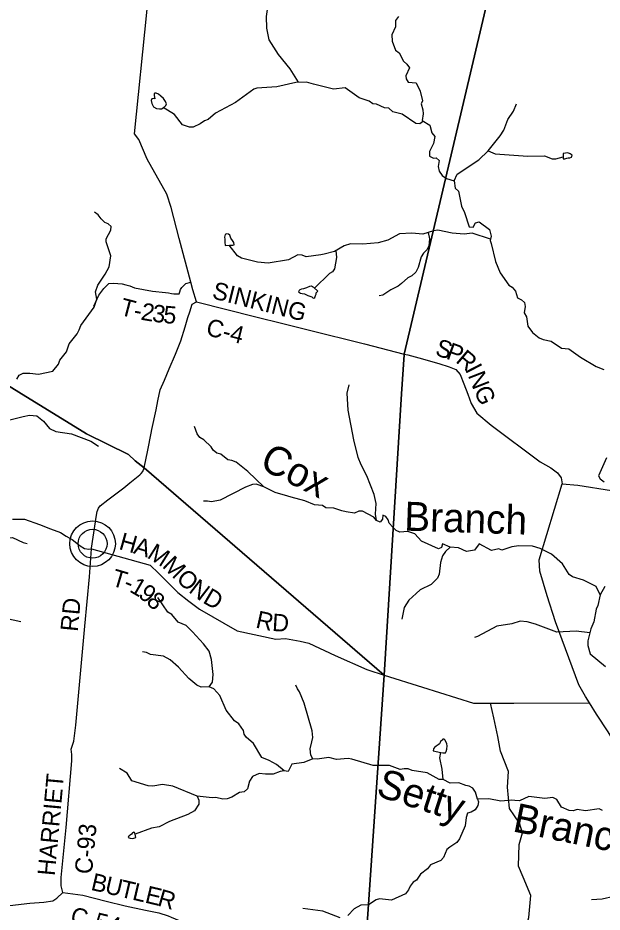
# Model space of a CAD drawing. Extents: x 1525783 to 1900577, y 218250 to 627376.
# Drawn here: x 1686297 to 1696377, y 391777 to 407202 of the extents above; entities that cross this region are included whole.
import ezdxf

# ---------------------------------------------------------------- set-up
doc = ezdxf.new("R2010")
doc.units = 0
for name, color, linetype in [('GM_X_County_Road', 7, 'Continuous'), ('GM_X_County_Road_Text', 7, 'Continuous'), ('GM_X_Minor_Lake', 7, 'Continuous'), ('GM_X_Minor_River', 7, 'Continuous'), ('GM_X_Minor_River_Text', 7, 'Continuous'), ('GM_X_Township', 7, 'Continuous'), ('GM_X_Township_Road', 7, 'Continuous'), ('GM_X_Township_Road_Text', 7, 'Continuous'), ('GM_X_Township_ROW', 7, 'Continuous'), ('GM_X_Unincorporated', 7, 'Continuous'), ('GM_X_Unincorporated_Location', 7, 'Continuous')]:
    doc.layers.add(name, color=color, linetype=linetype)

msp = doc.modelspace()

# ---------------------------------------------------------------- linework, layer by layer
at = {"layer": 'GM_X_County_Road'}
for points in [[(1689376, 402305), (1689315, 402509), (1689280, 402641), (1689079, 403395), (1688943, 403934), (1688868, 404164), (1688526, 404763), (1688383, 405107), (1688311, 405205), (1688519, 407298), (1688611, 408295), (1688572, 408507), (1688365, 408841), (1688235, 409123), (1688204, 409341), (1688156, 409567), (1688118, 409667), (1687991, 409731), (1687933, 409730), (1688006, 410518), (1688100, 411267), (1688235, 412775)], [(1688231, 399183), (1688399, 399321), (1688426, 399344), (1688450, 399380), (1688475, 399440), (1688539, 399748), (1688594, 400037), (1688606, 400101), (1688681, 400443), (1688714, 400597), (1688751, 400786), (1688826, 400955), (1688907, 401149), (1689018, 401403), (1689108, 401634), (1689183, 401871), (1689230, 402035), (1689263, 402130), (1689303, 402265), (1689376, 402305)], [(1689376, 402305), (1690403, 402046), (1690870, 401929), (1691308, 401821), (1692276, 401581), (1692963, 401404), (1693024, 401388)], [(1693024, 401388), (1693213, 401340), (1693562, 401238), (1693736, 401183), (1693851, 401135), (1693925, 401052), (1693991, 400892), (1694058, 400714), (1694117, 400550), (1694218, 400382), (1694460, 400177), (1695307, 399545), (1695493, 399438), (1695608, 399356), (1695669, 399269), (1695689, 399162), (1695956, 399142), (1696541, 399047)], [(1687568, 398044), (1687569, 398056), (1687654, 398627), (1687663, 398687), (1687686, 398743), (1687718, 398784), (1687848, 398890), (1688123, 399094), (1688231, 399183)], [(1698028, 391638), (1697920, 392012), (1697790, 392354), (1697577, 392945), (1697433, 393255), (1697123, 393824), (1697042, 393959), (1696781, 394389), (1696480, 394888), (1696280, 395190), (1696157, 395389), (1696091, 395495), (1695978, 395695), (1695575, 396785), (1695426, 397233), (1695305, 397657), (1695289, 397853), (1695689, 399162)], [(1686205, 398555), (1686411, 398553), (1686672, 398464), (1686857, 398391), (1687035, 398324), (1687130, 398264), (1687232, 398203), (1687313, 398143), (1687373, 398095), (1687449, 398052), (1687519, 398040), (1687568, 398041)], [(1687072, 392116), (1687042, 392230), (1687041, 392376), (1687128, 393236), (1687229, 394385), (1687226, 394497), (1687217, 394589), (1687264, 394726), (1687299, 395003), (1687452, 396709), (1687535, 397559), (1687568, 398041), (1687568, 398044)], [(1685565, 391822), (1686504, 391934), (1686746, 391947), (1686902, 391970), (1686968, 392017), (1687072, 392116)], [(1687072, 392116), (1687416, 392069), (1687819, 391968), (1688146, 391886), (1688497, 391812), (1688729, 391763), (1688891, 391710), (1688944, 391692), (1689179, 391593), (1689456, 391475), (1689615, 391400), (1689920, 391205), (1690158, 391026), (1690421, 390836), (1690582, 390732), (1690716, 390675), (1690963, 390608), (1691148, 390543), (1691337, 390467), (1691483, 390415), (1691549, 390398), (1691691, 390411), (1692001, 390450)]]:
    msp.add_lwpolyline(points, dxfattribs=at)
at = {"layer": 'GM_X_Minor_Lake'}
for points in [[(1688819, 405663), (1688847, 405692), (1688860, 405718), (1688846, 405760), (1688807, 405811), (1688763, 405853), (1688721, 405886), (1688682, 405902), (1688660, 405902), (1688650, 405896), (1688651, 405862), (1688661, 405806), (1688633, 405810), (1688611, 405807), (1688598, 405779), (1688610, 405724), (1688637, 405668), (1688689, 405642), (1688741, 405635), (1688773, 405633)], [(1688773, 405633), (1688819, 405663)], [(1695706, 404772), (1695732, 404771), (1695752, 404775), (1695768, 404783), (1695790, 404787), (1695818, 404789), (1695846, 404798), (1695861, 404832), (1695825, 404860), (1695787, 404873), (1695747, 404871), (1695707, 404864)], [(1695707, 404864), (1695707, 404804), (1695706, 404772)], [(1689951, 403281), (1690006, 403279), (1690026, 403285), (1690024, 403325), (1689999, 403365), (1689973, 403403), (1689952, 403457), (1689928, 403472), (1689896, 403478), (1689872, 403466), (1689862, 403422), (1689865, 403384), (1689867, 403334), (1689874, 403278)], [(1689874, 403278), (1689951, 403281)], [(1691401, 402550), (1691383, 402563), (1691361, 402573), (1691327, 402571), (1691275, 402546), (1691225, 402528), (1691193, 402520), (1691163, 402509), (1691151, 402499), (1691139, 402477), (1691174, 402451), (1691202, 402450), (1691242, 402442), (1691274, 402424), (1691298, 402411), (1691334, 402401), (1691366, 402389), (1691387, 402374), (1691405, 402368), (1691423, 402380), (1691432, 402414), (1691442, 402438), (1691446, 402458), (1691472, 402488)], [(1691472, 402488), (1691401, 402550)], [(1693595, 394533), (1693629, 394525), (1693653, 394525), (1693677, 394522), (1693689, 394548), (1693699, 394588), (1693704, 394644), (1693696, 394680), (1693669, 394741), (1693651, 394759), (1693631, 394763), (1693615, 394745), (1693597, 394731), (1693583, 394701), (1693572, 394682), (1693548, 394664), (1693516, 394640), (1693486, 394614), (1693466, 394591), (1693461, 394558)], [(1693461, 394558), (1693595, 394533)], [(1688321, 393124), (1688309, 393150), (1688299, 393157), (1688277, 393147), (1688257, 393123), (1688235, 393103), (1688215, 393093), (1688205, 393083), (1688197, 393066), (1688236, 393053), (1688272, 393047), (1688300, 393053), (1688330, 393066)], [(1688330, 393066), (1688321, 393124)]]:
    msp.add_lwpolyline(points, dxfattribs=at)
at = {"layer": 'GM_X_Minor_River'}
for points in [[(1691138, 406091), (1690997, 406323), (1690792, 406570), (1690630, 406823), (1690595, 407026), (1690585, 407226), (1690615, 407428), (1690618, 407576), (1690573, 407647), (1690459, 407692), (1690323, 407805), (1690146, 407893)], [(1692866, 407226), (1692815, 407156), (1692814, 407046), (1692747, 406910), (1692752, 406800), (1692812, 406644), (1692876, 406599), (1692952, 406454), (1693010, 406405), (1693055, 406343), (1692992, 406204), (1692997, 406149), (1693030, 406091), (1693166, 406082), (1693237, 405939), (1693277, 405772), (1693256, 405719), (1693283, 405614), (1693291, 405546), (1693270, 405434), (1693403, 405353), (1693441, 405220), (1693489, 405158), (1693469, 405036), (1693398, 404898), (1693397, 404818), (1693465, 404780), (1693515, 404791), (1693566, 404743), (1693551, 404639), (1693565, 404561), (1693616, 404482), (1693693, 404429), (1693827, 404392), (1693841, 404266), (1693897, 404213), (1693950, 403954), (1694005, 403846), (1694082, 403597), (1694152, 403592), (1694195, 403666), (1694253, 403687), (1694436, 403553), (1694460, 403437), (1694446, 403363), (1694465, 403309), (1694540, 403000), (1694616, 402807), (1694766, 402589), (1694827, 402555), (1694880, 402486), (1694915, 402372), (1694985, 402341), (1695040, 402294), (1695050, 402226), (1695033, 402116), (1695072, 402046), (1695096, 401883), (1695177, 401773), (1695290, 401685), (1695362, 401657), (1695497, 401623), (1695678, 401505), (1695801, 401496), (1696004, 401350), (1696274, 401187)], [(1693296, 405418), (1693231, 405377), (1693165, 405381), (1692925, 405544), (1692766, 405581), (1692698, 405644), (1692623, 405653), (1692485, 405716), (1692421, 405721), (1692358, 405765), (1692185, 405823), (1691941, 405998), (1691741, 405970), (1691396, 406061), (1691278, 406094), (1691095, 406090), (1690764, 406011), (1690422, 405991), (1690370, 405973), (1690052, 405744), (1689707, 405560), (1689580, 405449), (1689514, 405425), (1689443, 405374), (1689323, 405315), (1689259, 405318), (1689140, 405357), (1689000, 405536), (1688805, 405654)], [(1693827, 404392), (1693874, 404506), (1694252, 404754), (1694413, 404908), (1694619, 405165), (1694682, 405268), (1694748, 405450), (1694849, 405595), (1694901, 405722)], [(1694413, 404908), (1694530, 404855), (1695095, 404816), (1695381, 404821), (1695516, 404771), (1695578, 404771), (1695707, 404807)], [(1686279, 400970), (1686318, 401042), (1686388, 401073), (1686506, 401076), (1686650, 401054), (1686902, 401106), (1686997, 401231), (1687022, 401297), (1687133, 401440), (1687182, 401577), (1687320, 401750), (1687357, 401820), (1687381, 401894), (1687612, 402210), (1687659, 402353), (1687639, 402478), (1687674, 402593), (1687804, 402784), (1687871, 402906), (1687899, 403096), (1687821, 403342), (1687820, 403393), (1687903, 403538), (1687904, 403602), (1687854, 403652), (1687800, 403671), (1687735, 403734), (1687682, 403806), (1687620, 403853)], [(1694451, 403388), (1694135, 403490), (1693997, 403472), (1693788, 403486), (1693542, 403538), (1693468, 403529), (1693284, 403469), (1693096, 403488), (1692881, 403477), (1692678, 403368), (1692515, 403324), (1692246, 403301), (1692036, 403307), (1691924, 403270), (1691757, 403175), (1691581, 403125), (1691523, 403114), (1691271, 403080), (1691201, 403107), (1691127, 403114), (1690966, 403031), (1690618, 402969), (1690431, 402988), (1690154, 403057), (1690086, 403100), (1689945, 403281)], [(1693373, 403498), (1693401, 403393), (1693386, 403263), (1693355, 403200), (1693295, 403144), (1693254, 403081), (1693204, 402895), (1693164, 402815), (1693095, 402752), (1693025, 402721), (1692914, 402620), (1692858, 402572), (1692731, 402511), (1692596, 402421), (1692530, 402407)], [(1691780, 403188), (1691792, 403069), (1691762, 402875), (1691723, 402821), (1691671, 402792), (1691414, 402540)], [(1696274, 401187), (1696409, 401136)], [(1692482, 398535), (1692469, 398641), (1692481, 398825), (1692442, 398982), (1692318, 399303), (1692220, 399492), (1692167, 399619), (1692092, 399926), (1691997, 400433), (1691978, 400727), (1692010, 400871)], [(1685837, 400306), (1685939, 400293), (1686010, 400254), (1686114, 400259), (1686389, 400328), (1686497, 400349), (1686623, 400336), (1686740, 400245), (1686844, 400118), (1686952, 400069), (1687223, 400026), (1687555, 399902), (1687690, 399813)], [(1696345, 397252), (1696272, 397391), (1696055, 397503), (1695868, 397563), (1695811, 397603), (1695691, 397785), (1695503, 397949), (1695308, 398051), (1695178, 398088), (1694941, 398098), (1694821, 398077), (1694648, 398021), (1694595, 398042), (1694466, 398017), (1694256, 398131), (1694177, 398020), (1694037, 397999), (1693898, 398059), (1693758, 398074), (1693621, 398129), (1693606, 398069), (1693556, 398046), (1693261, 398177), (1693145, 398302), (1693025, 398341), (1692885, 398331), (1692822, 398359), (1692768, 398416), (1692705, 398485), (1692688, 398541), (1692644, 398601), (1692593, 398624), (1692588, 398554), (1692550, 398502), (1692482, 398535), (1692436, 398587), (1692242, 398691), (1692178, 398692), (1692106, 398659), (1691962, 398682), (1691888, 398697), (1691749, 398746), (1691613, 398750), (1691550, 398792), (1691416, 398800), (1691245, 398869), (1691010, 398932), (1690952, 398952), (1690737, 399016), (1690538, 399114), (1690265, 399377), (1690063, 399539), (1689987, 399570), (1689919, 399581), (1689796, 399676), (1689731, 399695), (1689665, 399748), (1689634, 399804), (1689507, 399921), (1689438, 399964), (1689392, 400026), (1689344, 400153)], [(1696450, 399612), (1696313, 399302), (1696345, 399251), (1696410, 399199)], [(1690538, 399114), (1690411, 399160), (1690343, 399156), (1690222, 399110), (1689785, 398884), (1689638, 398855), (1689567, 398866), (1689499, 398865)], [(1685044, 398064), (1685161, 398039), (1685229, 398048), (1685368, 398115), (1685510, 398125), (1685829, 398262), (1685964, 398211), (1686206, 398241), (1686387, 398155), (1686459, 398136)], [(1693758, 398074), (1693673, 397995), (1693625, 397923), (1693591, 397805), (1693567, 397605), (1693539, 397538), (1693428, 397429), (1693235, 397335), (1693171, 397275), (1693042, 397158), (1692960, 397033), (1692922, 396829)], [(1696422, 397395), (1696345, 397252), (1696305, 397064), (1696272, 397000), (1696232, 396787), (1696185, 396663), (1696166, 396593), (1696133, 396457), (1696130, 396377), (1696169, 396235), (1696436, 396012)], [(1689599, 395663), (1689655, 395741), (1689665, 395877), (1689639, 396137), (1689595, 396276), (1689502, 396407), (1689310, 396613), (1689200, 396720), (1689064, 396777), (1688952, 396910), (1688884, 396951), (1688709, 397203)], [(1684881, 396254), (1684944, 396414), (1684946, 396482), (1684989, 396607), (1685044, 396675), (1685213, 396775), (1685494, 396773), (1685605, 396796), (1685675, 396821), (1685813, 396831), (1685939, 396862), (1686081, 396849), (1686350, 396792)], [(1696166, 396593), (1695927, 396624), (1695593, 396605), (1695229, 396743), (1695082, 396786), (1694962, 396795), (1694817, 396751), (1694563, 396711), (1694226, 396532), (1694176, 396513)], [(1690893, 394214), (1690760, 394321), (1690633, 394394), (1690504, 394446), (1690364, 394685), (1690235, 394796), (1690200, 394849), (1690187, 394907), (1690112, 395024), (1690036, 395075), (1689892, 395260), (1689779, 395515), (1689678, 395630), (1689599, 395663), (1689461, 395659), (1689387, 395693), (1689249, 395805), (1689067, 396005), (1688922, 396128), (1688809, 396191), (1688583, 396218), (1688518, 396254), (1688448, 396269)], [(1696386, 393531), (1696326, 393556), (1696088, 393524), (1695948, 393548), (1695878, 393522), (1695810, 393531), (1695677, 393588), (1695596, 393719), (1695529, 393756), (1695391, 393737), (1695112, 393772), (1694951, 393699), (1694873, 393704), (1694821, 393709), (1694629, 393693), (1694424, 393733), (1694228, 393727), (1694191, 393845), (1694144, 393913), (1694081, 393950), (1694027, 393961), (1693905, 394008), (1693757, 394003), (1693634, 394063), (1693564, 394065), (1693360, 394177), (1693098, 394222), (1693031, 394251), (1692959, 394251), (1692893, 394236), (1692708, 394306), (1692426, 394307), (1692057, 394414), (1691994, 394427), (1691796, 394409), (1691662, 394446), (1691458, 394414), (1691386, 394419), (1691353, 394487), (1691342, 394591), (1691369, 394713), (1691386, 394787), (1691373, 394905), (1691234, 395381), (1691158, 395576), (1691123, 395626), (1691091, 395693)], [(1693634, 394063), (1693620, 394241), (1693576, 394439), (1693595, 394533)], [(1691386, 394419), (1691232, 394356), (1691024, 394330), (1690963, 394205), (1690893, 394214), (1690821, 394204), (1690704, 394157), (1690571, 394157), (1690461, 394168), (1690346, 394115), (1690296, 394033), (1690258, 393902), (1690200, 393852), (1690120, 393843), (1689987, 393762), (1689907, 393733), (1689833, 393728), (1689712, 393753), (1689650, 393746), (1689390, 393778), (1688968, 393952), (1688795, 393978), (1688623, 393948), (1688543, 393955), (1688264, 394043), (1688180, 394174), (1688049, 394254)], [(1689390, 393778), (1689420, 393708), (1689421, 393640), (1689342, 393523), (1689231, 393458), (1688912, 393341), (1688732, 393248), (1688604, 393226), (1688321, 393124)], [(1694228, 393727), (1694246, 393682), (1694233, 393614), (1694188, 393543), (1694120, 393499), (1694056, 393482), (1694029, 393408), (1694014, 393264), (1693918, 393039), (1693871, 392980), (1693749, 392899), (1693696, 392859), (1693639, 392720), (1693592, 392666), (1693416, 392594), (1693367, 392524), (1693244, 392434), (1693172, 392328), (1693119, 392295), (1693063, 392223), (1693036, 392161), (1692987, 392092), (1692741, 391982), (1692535, 392006), (1692481, 391991), (1692344, 391904), (1692212, 391899), (1692100, 391833), (1691991, 391720)], [(1698703, 392564), (1698492, 392560), (1698351, 392495), (1698229, 392463), (1697803, 392465), (1697661, 392424), (1697474, 392304), (1697270, 392230), (1697137, 392141), (1697005, 392094), (1696837, 392082), (1696769, 392047), (1696581, 392045), (1696379, 392001), (1696193, 391990)], [(1691857, 391677), (1691556, 391792), (1691211, 391841)]]:
    msp.add_lwpolyline(points, dxfattribs=at)
at = {"layer": 'GM_X_Township'}
for points in [[(1699164, 420184), (1695772, 414672), (1695360, 414002), (1694863, 409438), (1694651, 408579), (1692963, 401404), (1692960, 401391), (1692916, 400719), (1692619, 395862), (1688475, 399440), (1688322, 399564), (1688208, 399673), (1687479, 400030), (1682729, 402947), (1680396, 404440), (1678915, 405396), (1678615, 405583), (1678537, 406652), (1678285, 411417), (1677923, 418276)], [(1708828, 383819), (1700474, 382353), (1699796, 382245), (1691630, 380967), (1691819, 383865), (1692250, 390483), (1692619, 395862), (1692916, 400719), (1692960, 401391), (1692963, 401404), (1694651, 408579), (1694863, 409438), (1695360, 414002), (1695772, 414672), (1699164, 420184)], [(1682729, 402947), (1687479, 400030), (1688208, 399673), (1688322, 399564), (1688475, 399440), (1692619, 395862), (1692250, 390483), (1691819, 383865), (1691630, 380967), (1691562, 380956), (1691232, 380887), (1691184, 380874), (1689080, 380492), (1687556, 380216), (1684870, 379728)]]:
    msp.add_lwpolyline(points, dxfattribs=at)
at = {"layer": 'GM_X_Township_Road'}
for points in [[(1687605, 402229), (1687691, 402417), (1687782, 402535), (1687866, 402619), (1687944, 402625), (1688095, 402617), (1688159, 402599), (1688231, 402580), (1688310, 402547), (1688621, 402488), (1688842, 402468), (1688898, 402458), (1688950, 402447), (1688988, 402445), (1689048, 402442), (1689080, 402443), (1689092, 402475), (1689101, 402519), (1689123, 402550), (1689161, 402585), (1689195, 402621), (1689280, 402641)], [(1687568, 398041), (1688581, 397761), (1688724, 397626), (1689057, 397293), (1689248, 397138), (1689433, 397004), (1690079, 396628), (1690749, 396484), (1690917, 396499), (1690980, 396487)], [(1690980, 396487), (1691166, 396450), (1691317, 396414), (1691770, 396205), (1692320, 395960), (1692334, 395956)], [(1692334, 395956), (1692619, 395862), (1693276, 395655), (1694157, 395382), (1694453, 395383), (1694853, 395384)], [(1694654, 390344), (1694835, 390841), (1695030, 391400), (1695113, 391684), (1695146, 392065), (1695015, 392380), (1695014, 392381)]]:
    msp.add_lwpolyline(points, dxfattribs=at)
at = {"layer": 'GM_X_Township_ROW'}
for points in [[(1695014, 392381), (1694937, 392567), (1694947, 392944), (1695002, 393143), (1694954, 393313), (1694780, 393566), (1694745, 393933), (1694762, 394204), (1694626, 394553), (1694578, 394808), (1694507, 395127), (1694453, 395383)], [(1694853, 395384), (1694855, 395384), (1696157, 395389)]]:
    msp.add_lwpolyline(points, dxfattribs=at)
at = {"layer": 'GM_X_Unincorporated'}
for radius in [393, 249]:
    msp.add_circle((1687586, 398132), radius, dxfattribs=at)
at = {"layer": 'GM_X_Unincorporated_Location'}
msp.add_line((1687586, 398132), (1687586, 398132), dxfattribs=at)

# ---------------------------------------------------------------- texts
at = {"layer": 'GM_X_County_Road_Text'}
for s, rotation, p in [('SINKING', 345.8419, (1689633, 402367)), ('C-4', 345.6293, (1689526, 401735)), ('S', 342.2608, (1693480, 401389)), ('P', 340.0579, (1693670, 401328)), ('R', 319.8077, (1693836, 401273)), ('I', 297.4099, (1694005, 401138)), ('N', 291.2941, (1694058, 401037)), ('G', 293.5838, (1694159, 400778)), ('RD', 84.585, (1687329, 396607)), ('HARRIET', 84.7633, (1686933, 392395)), ('C-93', 84.5277, (1687574, 392422)), ('B', 346.8091, (1687542, 392163)), ('U', 346.8058, (1687782, 392107)), ('T', 346.8094, (1688039, 392047)), ('L', 346.7995, (1688257, 391995)), ('E', 346.5614, (1688475, 391944)), ('R', 343.7045, (1688690, 391893)), ('C-54', 346.578, (1687185, 391582))]:
    msp.add_text(s, height=300, rotation=rotation, dxfattribs=at).set_placement(p)
at = {"layer": 'GM_X_Minor_River_Text'}
for s, rotation, p in [('Cox', 333.0063, (1690444, 399446)), ('Branch', 358.1138, (1692957, 398358)), ('Setty', 342.1148, (1692459, 393790)), ('Branch', 348.3924, (1694816, 393173))]:
    msp.add_text(s, height=500, rotation=rotation, dxfattribs=at).set_placement(p)
at = {"layer": 'GM_X_Township_Road_Text'}
for s, rotation, p in [('T', 345.391, (1688041, 402084)), ('-', 348.9878, (1688278, 402023)), ('2', 350.2013, (1688406, 401998)), ('3', 353.0148, (1688604, 401965)), ('5', 354.8002, (1688797, 401941)), ('H', 344.1647, (1688025, 398042)), ('A', 342.762, (1688277, 397970)), ('M', 327.783, (1688510, 397900)), ('M', 315.8041, (1688773, 397737)), ('T', 343.5713, (1687894, 397414)), ('1', 329.9234, (1688207, 397313)), ('O', 317.3529, (1689013, 397504)), ('N', 322.4971, (1689229, 397306)), ('-', 338.4334, (1688103, 397353)), ('9', 321.4645, (1688357, 397227)), ('D', 329.5874, (1689472, 397123)), ('8', 316.4058, (1688496, 397116)), ('R', 347.4538, (1690386, 396688)), ('D', 356.6837, (1690678, 396627))]:
    msp.add_text(s, height=300, rotation=rotation, dxfattribs=at).set_placement(p)

doc.saveas('drawing.dxf')
